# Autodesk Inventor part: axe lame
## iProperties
Shininess: 20.0
Angle Display Precision: 2
Document Length Units: 11269
Document Angle Units: 11279
Document Time Units: 11290
Document Mass Units: 11283
Document Length Units Precision: 3
Document Angle Units Precision: 2
Compacted: True
Created: 2002-04
Part Number: axe lame
Material: Par défaut
Document SubType Name: Modélisation
Designer: thchene
Density: 0.0
Volumn: 0.0
Area: 0.0
PropertySet Name: Model Information
Control State: 0
Master: False
Checked Out: False
Author: thchene
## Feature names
1. Révolution1 [Revolution]
2. Chanfrein1 [Chamfer]
3. Extrusion1
